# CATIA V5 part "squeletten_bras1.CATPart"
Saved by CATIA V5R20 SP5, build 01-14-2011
Part number: squelette_manivelle1
Publications: "LineForRevolute1", "LineForRevolute2", "PlaneForRevolute", "Droite.6", "Droite.7", "Droite.4"
Bounding box of the stored display mesh (mm): x -20 to 20, y -89.647 to 67.091, z -90.495 to 82.099
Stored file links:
  U:\Sauvegarde IFMA\squeletten_bras1.CATPart
  D:\rabany\a-IFMA\10-11\CFAO Usine numerique (ex MG)\TP03\exemple squelette\architect.CATProduct
  U:\Projet V11\assemblage_final_v2.CATProduct
  U:\Sauvegarde IFMA\squelette.CATProduct
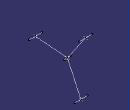
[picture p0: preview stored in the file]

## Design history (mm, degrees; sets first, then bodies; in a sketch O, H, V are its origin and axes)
Set1
  Point1: linked copy from another document
  Point2: linked copy from another document
  Plane1: linked copy from another document
  Point3: linked copy from another document
  Point4: linked copy from another document
Set2
  Line1: type PtPt, FirstPoint Point1, SecondPoint Point2
  Line2: type Normal, RefPoint Point1, RefSkin Plane1, Start -10, End 10
  Line3: type Normal, RefPoint Point2, RefSkin Plane1, Start -20, End 20
  Line4: type PtPt, FirstPoint Point1, SecondPoint Point3
  Line5: type PtPt, FirstPoint Point1, SecondPoint Point4
  Line6: type PtDir, RefPoint Point3, Direction Line2, Start -20, End 20
  Line7: type PtDir, RefPoint Point4, Direction Line2, Start -20, End 20
Body1 (main body)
